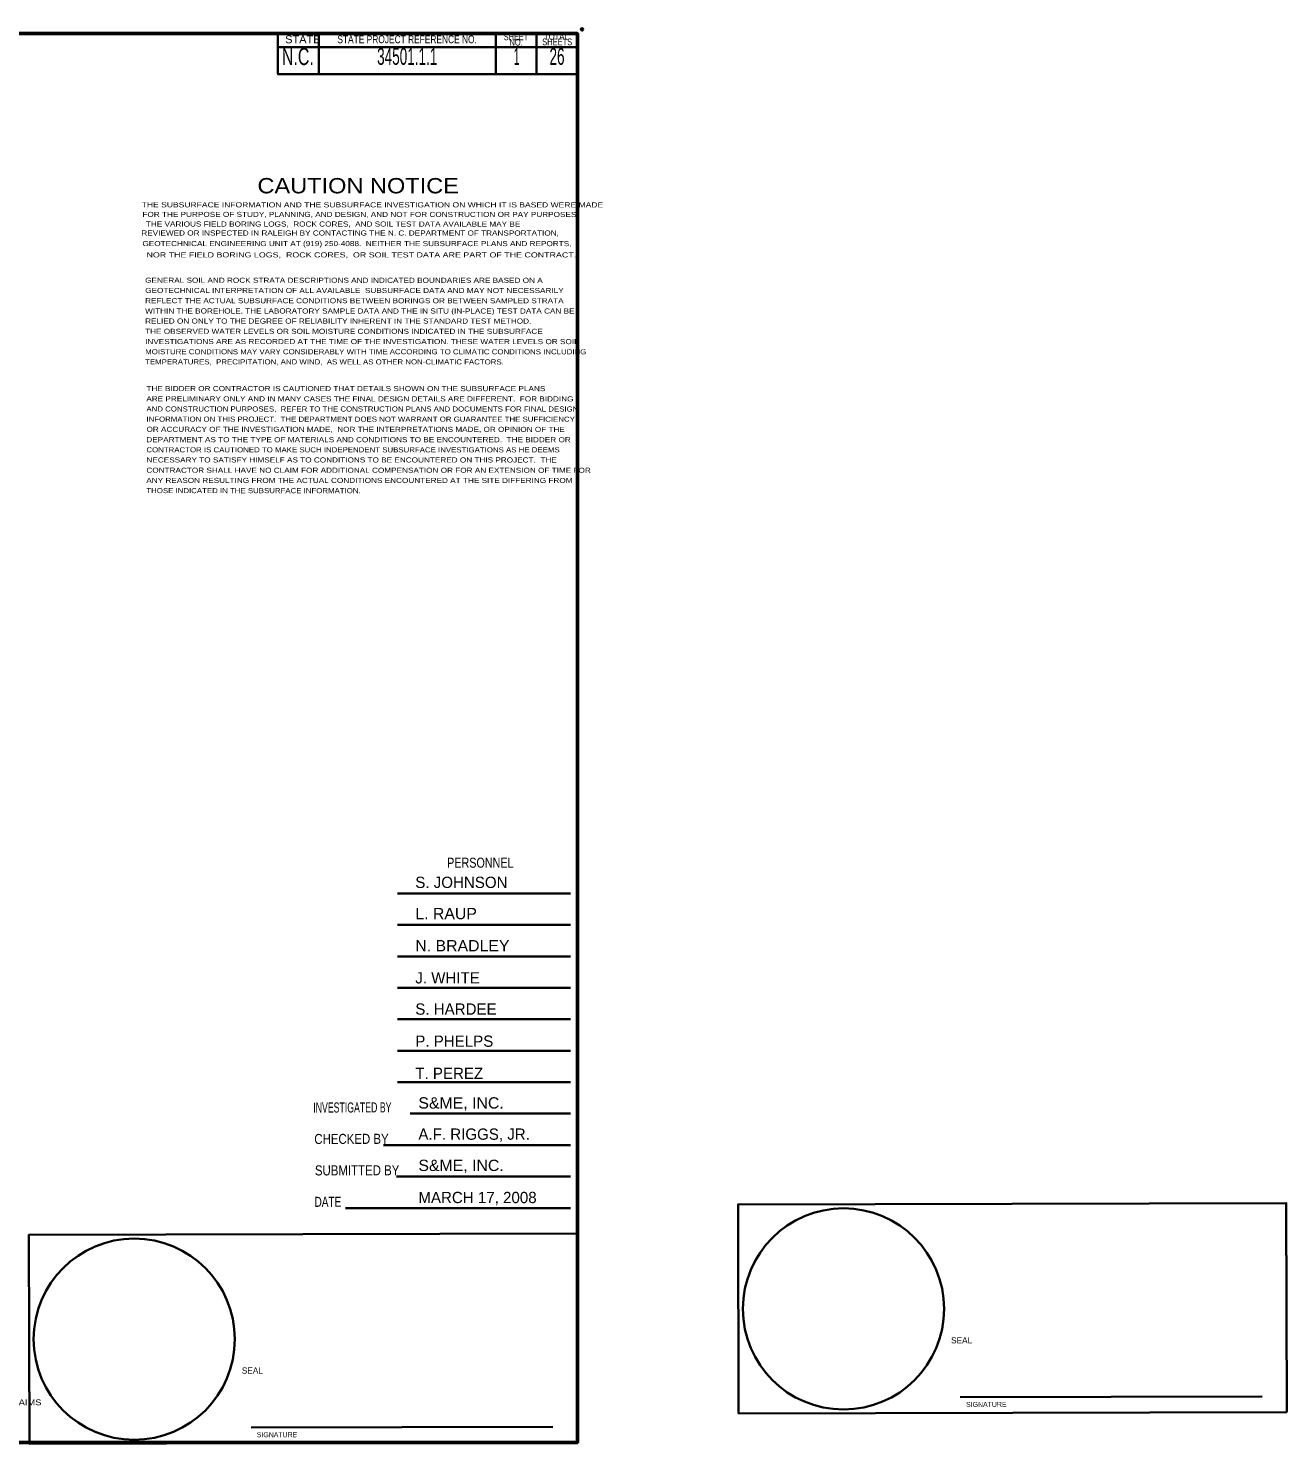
# Model space of a CAD drawing. Extents: x 278712 to 279914, y 171254 to 171792.
# Drawn here: x 278866.5 to 278960.1, y 171476 to 171581.3 of the extents above; entities that cross this region are included whole.
import ezdxf
from ezdxf.enums import TextEntityAlignment as Align

# ---------------------------------------------------------------- set-up
doc = ezdxf.new("R2010")
doc.units = 0
doc.header["$LTSCALE"] = 0.34
doc.header["$PDMODE"] = 32
doc.header["$PDSIZE"] = 0.17
doc.layers.add('23', color=7, linetype='Continuous', lineweight=35)
doc.layers.add('60', color=7, linetype='Continuous', lineweight=35)

msp = doc.modelspace()

# ---------------------------------------------------------------- linework, layer by layer
at = {"layer": '23'}
for p, q in [((278935.8371, 171479.4397), (278958.3011, 171479.4917)), ((278883.0366, 171477.1857), (278905.5006, 171477.2377))]:
    msp.add_line(p, q, dxfattribs=at)
for points in [[(278960.1381, 171478.3352), (278919.3381, 171478.2407), (278919.3021, 171493.7972), (278960.1026, 171493.8912)], [(278907.3376, 171476.0812), (278866.5376, 171475.9867), (278866.5016, 171491.5432), (278907.3021, 171491.6372)]]:
    msp.add_lwpolyline(points, close=True, dxfattribs=at)
for centre in [(278927.1453, 171486.0185), (278874.3448, 171483.7644)]:
    msp.add_circle(centre, 7.488, dxfattribs=at)
at = {"layer": '60'}
for p, q in [((278888.0764, 171580.9495), (278888.0764, 171577.9145)), ((278901.2554, 171580.9495), (278901.2554, 171577.9145)), ((278904.2964, 171580.9495), (278904.2964, 171577.9145)), ((278885.0344, 171579.9405), (278907.3376, 171579.9405)), ((278893.9379, 171516.9367), (278906.8336, 171516.9367)), ((278893.9379, 171514.5967), (278906.8336, 171514.5967)), ((278893.9379, 171512.2567), (278906.8336, 171512.2567)), ((278893.9379, 171509.9167), (278906.8336, 171509.9167)), ((278893.9379, 171507.5767), (278906.8336, 171507.5767)), ((278893.9379, 171505.2367), (278906.8336, 171505.2367)), ((278893.9379, 171502.8967), (278906.8336, 171502.8967)), ((278894.8871, 171500.5567), (278906.8336, 171500.5567)), ((278892.8989, 171498.2117), (278906.8336, 171498.2117)), ((278893.8691, 171495.8747), (278906.8336, 171495.8747)), ((278890.0739, 171493.5257), (278906.8336, 171493.5257))]:
    msp.add_line(p, q, dxfattribs=at)
at = {"layer": '60', "lineweight": 53}
msp.add_lwpolyline([(278756.0874, 171580.9495), (278907.3376, 171580.9495), (278907.3376, 171476.0812), (278756.0874, 171476.0812)], close=True, dxfattribs=at)
at = {"layer": '60'}
msp.add_lwpolyline([(278885.0344, 171580.9495), (278907.3376, 171580.9495), (278907.3376, 171577.9145), (278885.0344, 171577.9145)], close=True, dxfattribs=at)
msp.add_point((278907.6876, 171581.2545), dxfattribs=at)

# ---------------------------------------------------------------- texts
at = {"layer": '23'}
for s, height, p in [('SEAL', 0.4587, (278935.1541, 171483.4537)), ('SEAL', 0.4587, (278882.3536, 171481.1997)), ('SIGNATURE', 0.3744, (278936.2691, 171478.7197)), ('SIGNATURE', 0.3744, (278883.4686, 171476.4657))]:
    msp.add_text(s, height=height, rotation=0.132, dxfattribs=at).set_placement(p)
at = {"layer": '60'}
for s, height, rotation, width, p in [('STATE', 0.5824, 0.015, 1.05, (278886.8979, 171580.2268)), ('STATE PROJECT REFERENCE NO.', 0.5824, 0.015, 0.8, (278894.6598, 171580.2289)), ('SHEET', 0.4992, 0.015, 0.75, (278902.7644, 171580.4557)), ('TOTAL', 0.4992, 0.015, 0.85, (278905.7669, 171580.4847)), ('N.C.', 1.271, 0.015, 0.7, (278886.524, 171578.6068)), ('34501.1.1', 1.255, 0.015, 0.6, (278894.6663, 171578.619)), ('NO.', 0.4992, 0.015, 0.7, (278902.7706, 171580.0536)), ('1', 1.255, 0.015, 0.45, (278902.8075, 171578.6195)), ('SHEETS', 0.4992, 0.015, 0.7, (278905.8322, 171580.0787)), ('26', 1.255, 0.015, 0.6, (278905.8176, 171578.6196)), ('CAUTION NOTICE ', 1.14, 359.992, 1.15, (278891.2602, 171569.0546)), ('THE SUBSURFACE INFORMATION AND THE SUBSURFACE INVESTIGATION ON WHICH IT IS BASED WERE MADE', 0.3798, 359.992, 1.25, (278892.0767, 171568.0097)), ('FOR THE PURPOSE OF STUDY, PLANNING, AND DESIGN, AND NOT FOR CONSTRUCTION OR PAY PURPOSES. ', 0.3798, 359.992, 1.2, (278891.2736, 171567.2954)), ('REVIEWED OR INSPECTED IN RALEIGH BY CONTACTING THE N. C. DEPARTMENT OF TRANSPORTATION, ', 0.3798, 359.992, 1.2, (278890.4995, 171565.9137)), ('GEOTECHNICAL ENGINEERING UNIT AT (919) 250-4088.  NEITHER THE SUBSURFACE PLANS AND REPORTS,', 0.3798, 359.992, 1.2, (278890.9228, 171565.1261)), ('NOTE - BY HAVING REQUESTED THIS INFORMATION THE CONTRACTOR SPECIFICALLY WAIVES ANY CLAIMS', 0.4314, 359.992, 1.2, (278849.1248, 171478.8515))]:
    msp.add_text(s, height=height, rotation=rotation, dxfattribs=dict(at, width=width)).set_placement(p, align=Align.CENTER)
for s, height, rotation, width, p in [('THE VARIOUS FIELD BORING LOGS,  ROCK CORES,  AND SOIL TEST DATA AVAILABLE MAY BE ', 0.3798, 359.992, 1.2, (278875.2111, 171566.5822)), ('NOR THE FIELD BORING LOGS,  ROCK CORES,  OR SOIL TEST DATA ARE PART OF THE CONTRACT.', 0.3798, 359.992, 1.3, (278875.2561, 171564.2872)), ('GENERAL SOIL AND ROCK STRATA DESCRIPTIONS AND INDICATED BOUNDARIES ARE BASED ON A', 0.3798, 359.992, 1.2, (278875.1539, 171562.396)), ('GEOTECHNICAL INTERPRETATION OF ALL AVAILABLE  SUBSURFACE DATA AND MAY NOT NECESSARILY', 0.3798, 359.992, 1.2, (278875.1594, 171561.6375)), ('REFLECT THE ACTUAL SUBSURFACE CONDITIONS BETWEEN BORINGS OR BETWEEN SAMPLED STRATA ', 0.3798, 359.992, 1.2, (278875.1549, 171560.8737)), ('WITHIN THE BOREHOLE. THE LABORATORY SAMPLE DATA AND THE IN SITU (IN-PLACE) TEST DATA CAN BE', 0.3798, 359.992, 1.2, (278875.1549, 171560.1107)), ('RELIED ON ONLY TO THE DEGREE OF RELIABILITY INHERENT IN THE STANDARD TEST METHOD.', 0.3798, 359.992, 1.2, (278875.1549, 171559.3617)), ('THE OBSERVED WATER LEVELS OR SOIL MOISTURE CONDITIONS INDICATED IN THE SUBSURFACE ', 0.3798, 359.992, 1.2, (278875.1549, 171558.599)), ('INVESTIGATIONS ARE AS RECORDED AT THE TIME OF THE INVESTIGATION. THESE WATER LEVELS OR SOIL', 0.3798, 359.992, 1.2, (278875.1549, 171557.835)), ('TEMPERATURES,  PRECIPITATION, AND WIND,  AS WELL AS OTHER NON-CLIMATIC FACTORS.', 0.3798, 359.992, 1.15, (278875.1504, 171556.3232)), ('MOISTURE CONDITIONS MAY VARY CONSIDERABLY WITH TIME ACCORDING TO CLIMATIC CONDITIONS INCLUDING', 0.3798, 359.992, 1.15, (278875.1601, 171557.0765)), ('THE BIDDER OR CONTRACTOR IS CAUTIONED THAT DETAILS SHOWN ON THE SUBSURFACE PLANS', 0.3798, 359.992, 1.2, (278875.2491, 171554.3345)), ('ARE PRELIMINARY ONLY AND IN MANY CASES THE FINAL DESIGN DETAILS ARE DIFFERENT.  FOR BIDDING', 0.3798, 359.992, 1.2, (278875.2439, 171553.5705)), ('AND CONSTRUCTION PURPOSES,  REFER TO THE CONSTRUCTION PLANS AND DOCUMENTS FOR FINAL DESIGN', 0.3798, 359.992, 1.15, (278875.2491, 171552.8172)), ('INFORMATION ON THIS PROJECT.  THE DEPARTMENT DOES NOT WARRANT OR GUARANTEE THE SUFFICIENCY', 0.3798, 359.992, 1.15, (278875.2491, 171552.0587)), ('OR ACCURACY OF THE INVESTIGATION MADE,  NOR THE INTERPRETATIONS MADE, OR OPINION OF THE ', 0.3793, 359.992, 1.2, (278875.2544, 171551.3002)), ('DEPARTMENT AS TO THE TYPE OF MATERIALS AND CONDITIONS TO BE ENCOUNTERED.  THE BIDDER OR', 0.3798, 359.992, 1.2, (278875.2446, 171550.532)), ('CONTRACTOR IS CAUTIONED TO MAKE SUCH INDEPENDENT SUBSURFACE INVESTIGATIONS AS HE DEEMS', 0.3798, 359.992, 1.15, (278875.2499, 171549.7777)), ('NECESSARY TO SATISFY HIMSELF AS TO CONDITIONS TO BE ENCOUNTERED ON THIS PROJECT.  THE', 0.3798, 359.992, 1.2, (278875.2551, 171549.0245)), ('CONTRACTOR SHALL HAVE NO CLAIM FOR ADDITIONAL COMPENSATION OR FOR AN EXTENSION OF TIME FOR', 0.3798, 359.992, 1.2, (278875.2499, 171548.2562)), ('ANY REASON RESULTING FROM THE ACTUAL CONDITIONS ENCOUNTERED AT THE SITE DIFFERING FROM ', 0.3798, 359.992, 1.2, (278875.2456, 171547.4977)), ('THOSE INDICATED IN THE SUBSURFACE INFORMATION.', 0.3796, 359.992, 1.15, (278875.2456, 171546.739)), ('PERSONNEL', 0.7488, 0.132, 0.8, (278897.6389, 171518.8535)), ('INVESTIGATED BY', 0.7488, 0.132, 0.65, (278887.6709, 171500.6337)), ('CHECKED BY', 0.7488, 0.132, 0.85, (278887.7509, 171498.2937)), ('SUBMITTED BY', 0.7488, 0.132, 0.85, (278887.7939, 171495.9537)), ('DATE', 0.7488, 0.132, 0.75, (278887.7619, 171493.6137))]:
    msp.add_text(s, height=height, rotation=rotation, dxfattribs=dict(at, width=width)).set_placement(p)
for s, p in [('S. JOHNSON', (278895.2669, 171517.3505)), ('J. WHITE', (278895.2669, 171510.2435)), ('S. HARDEE', (278895.2669, 171507.9185)), ('P. PHELPS', (278895.2669, 171505.5275)), ('T. PEREZ', (278895.2669, 171503.1365)), ('A.F. RIGGS, JR.', (278895.4971, 171498.6087)), ('MARCH 17, 2008', (278895.4971, 171493.8927))]:
    msp.add_text(s, height=0.84, dxfattribs=at).set_placement(p)
at = {"layer": '60', "width": 1.05}
for s, p in [('L. RAUP', (278895.2669, 171515.0255)), ('N. BRADLEY', (278895.2669, 171512.6345)), ('S&ME, INC.', (278895.4971, 171500.9337)), ('S&ME, INC.', (278895.4971, 171496.2837))]:
    msp.add_text(s, height=0.84, dxfattribs=at).set_placement(p)

doc.saveas('drawing.dxf')
